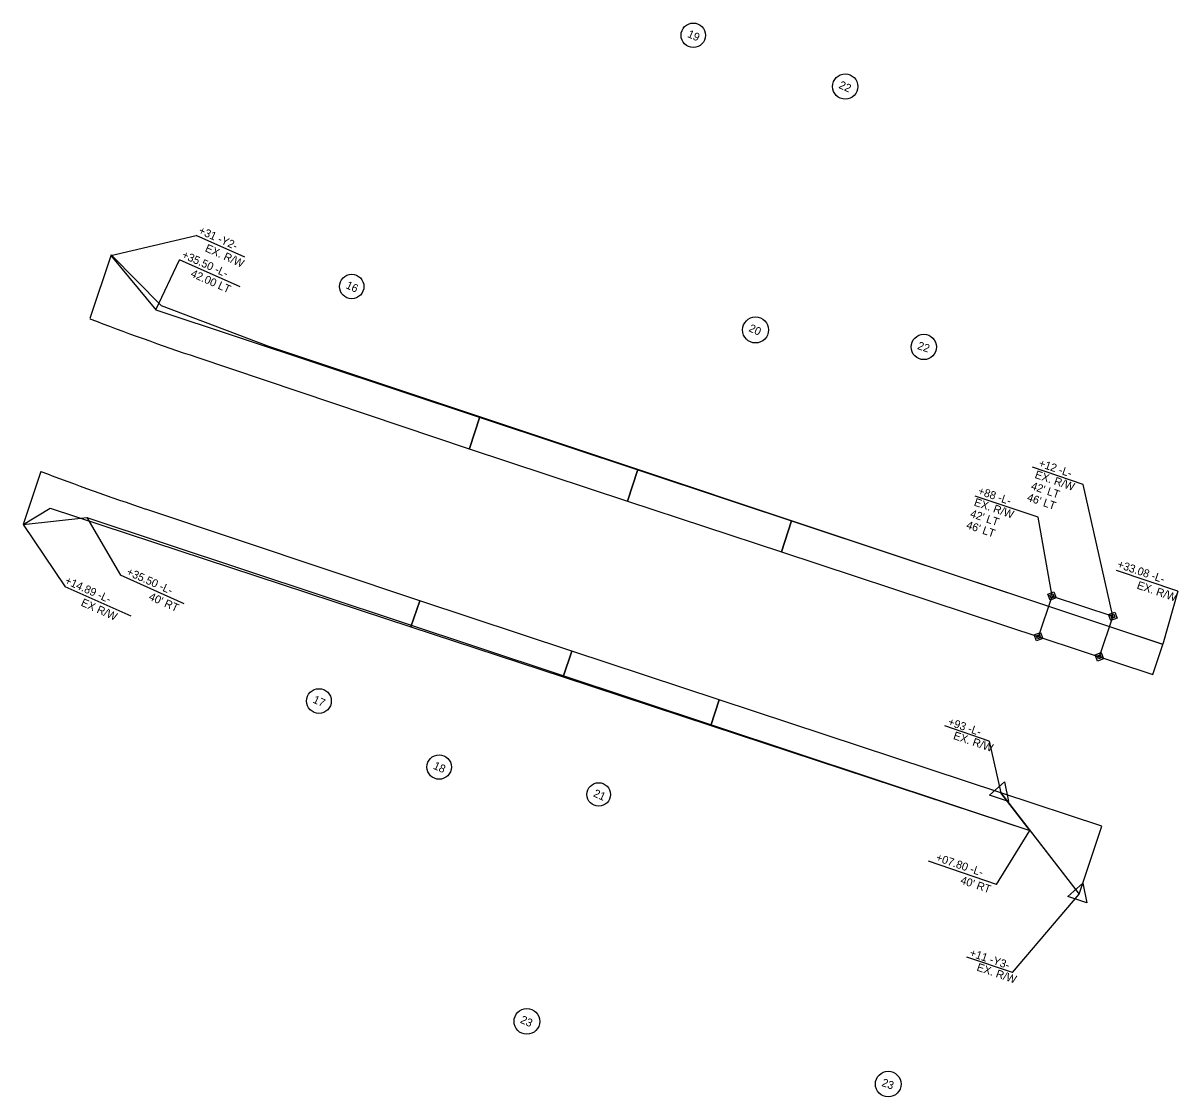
# Model space of a CAD drawing. Extents: x 2298011 to 2299093, y 599361 to 600353.
# Drawn here: x 2298660.4 to 2299093.1, y 599360.9 to 599763.4 of the extents above; entities that cross this region are included whole.
import ezdxf

# ---------------------------------------------------------------- set-up
doc = ezdxf.new("R2010")
doc.units = 0
for name, color, linetype in [('Prop Easement Construction', 7, 'Continuous'), ('Prop Easement Construction Station Offsets', 7, 'Continuous'), ('Prop Easement Permanent Drainage', 7, 'Continuous'), ('Prop Easement Permanent Drainage Station Offsets', 7, 'Continuous'), ('Prop Parcel Number Text', 7, 'Continuous'), ('Prop ROW Marker CELL', 7, 'Continuous'), ('Prop ROW Permanent Easement CELL', 7, 'Continuous'), ('Prop ROW RW Lines', 7, 'Continuous'), ('Prop ROW Station Offsets', 7, 'Continuous'), ('Scratch_Level_3', 7, 'Continuous'), ('Scratch_Level_6', 7, 'Continuous')]:
    doc.layers.add(name, color=color, linetype=linetype)

msp = doc.modelspace()

# ---------------------------------------------------------------- linework, layer by layer
at = {"layer": 'Prop Easement Construction'}
for p, q in [((2298693.31, 599676.25), (2298710.13, 599655.85)), ((2298710.13, 599655.85), (2299044.68, 599544.8)), ((2298660.37, 599575.48), (2298684.3, 599578.03)), ((2298684.3, 599578.03), (2299037.64, 599460.74)), ((2299067.46, 599537.24), (2299087.47, 599530.6))]:
    msp.add_line(p, q, dxfattribs=at)
at = {"layer": 'Prop Easement Construction Station Offsets'}
for p, q in [((2298743.43, 599675.6), (2298725.17, 599683.76)), ((2298741.77, 599664.48), (2298718.94, 599674.67)), ((2298720.77, 599545.73), (2298696.87, 599556.4)), ((2299093.11, 599550.44), (2299070.12, 599558.25)), ((2298700.86, 599541.03), (2298676.1, 599552.08)), ((2299025.16, 599440.51), (2298999.61, 599449.18))]:
    msp.add_line(p, q, dxfattribs=at)
for points in [[(2298693.31, 599676.25), (2298725.17, 599683.76)], [(2298710.13, 599655.85), (2298718.94, 599674.67)], [(2298684.3, 599578.03), (2298696.87, 599556.4)], [(2298660.37, 599575.48), (2298676.1, 599552.08)], [(2299093.11, 599550.44), (2299087.47, 599530.6)], [(2299025.16, 599440.51), (2299037.64, 599460.74)]]:
    msp.add_lwpolyline(points, dxfattribs=at)
at = {"layer": 'Prop Easement Permanent Drainage'}
for p, q in [((2299040.88, 599533.35), (2299045.94, 599548.6)), ((2299045.94, 599548.6), (2299068.72, 599541.04)), ((2299068.72, 599541.04), (2299063.67, 599525.82))]:
    msp.add_line(p, q, dxfattribs=at)
at = {"layer": 'Prop Easement Permanent Drainage Station Offsets'}
for p, q in [((2299057.56, 599590.48), (2299038.62, 599596.91)), ((2299068.72, 599541.04), (2299057.56, 599590.48)), ((2299040.69, 599578.12), (2299017.17, 599586.11))]:
    msp.add_line(p, q, dxfattribs=at)
msp.add_lwpolyline([(2299045.94, 599548.6), (2299040.69, 599578.12)], dxfattribs=at)
at = {"layer": 'Prop Parcel Number Text'}
for centre, radius in [((2298911.51, 599758.82), 4.57), ((2298968.45, 599739.59), 4.74), ((2298783.52, 599664.64), 4.58), ((2298934.85, 599648.36), 4.87), ((2298997.89, 599641.98), 4.74), ((2298771.23, 599509.25), 4.64), ((2298816.28, 599484.51), 4.58), ((2298876.06, 599474.24), 4.41), ((2298849.14, 599389.17), 4.81), ((2298984.55, 599365.67), 4.81)]:
    msp.add_circle(centre, radius, dxfattribs=at)
at = {"layer": 'Prop ROW Marker CELL'}
for p, q in [((2299045.94, 599548.6), (2299045.94, 599548.6)), ((2299068.72, 599541.04), (2299068.72, 599541.04)), ((2299040.88, 599533.35), (2299040.88, 599533.35)), ((2299063.67, 599525.82), (2299063.67, 599525.82)), ((2299026.73, 599474.84), (2299026.73, 599474.84)), ((2299056.1, 599436.88), (2299056.1, 599436.88))]:
    msp.add_line(p, q, dxfattribs=at)
for points in [[(2299022.48, 599474), (2299028.12, 599478.93), (2299029.58, 599471.59)], [(2299051.86, 599436.04), (2299057.49, 599440.97), (2299058.96, 599433.63)]]:
    msp.add_lwpolyline(points, close=True, dxfattribs=at)
at = {"layer": 'Prop ROW Permanent Easement CELL'}
for points in [[(2299045.24, 599547.02), (2299044.36, 599549.3), (2299046.64, 599550.18), (2299047.52, 599547.89)], [(2299045.59, 599547.81), (2299045.15, 599548.95), (2299046.29, 599549.39), (2299046.73, 599548.25)], [(2299068.01, 599539.46), (2299067.14, 599541.74), (2299069.42, 599542.61), (2299070.3, 599540.33)], [(2299068.37, 599540.25), (2299067.93, 599541.39), (2299069.07, 599541.83), (2299069.51, 599540.68)], [(2299040.18, 599531.78), (2299039.3, 599534.06), (2299041.58, 599534.93), (2299042.46, 599532.65)], [(2299040.53, 599532.56), (2299040.09, 599533.71), (2299041.23, 599534.14), (2299041.67, 599533)], [(2299062.96, 599524.25), (2299062.09, 599526.53), (2299064.37, 599527.4), (2299065.25, 599525.12)], [(2299063.32, 599525.04), (2299062.88, 599526.18), (2299064.02, 599526.61), (2299064.46, 599525.47)]]:
    msp.add_lwpolyline(points, close=True, dxfattribs=at)
at = {"layer": 'Prop ROW RW Lines'}
msp.add_line((2299026.73, 599474.84), (2299056.1, 599436.88), dxfattribs=at)
at = {"layer": 'Prop ROW Station Offsets'}
for p, q in [((2299022.42, 599494.26), (2299005.79, 599499.91)), ((2299031.18, 599407.45), (2299013.96, 599413.3))]:
    msp.add_line(p, q, dxfattribs=at)
for points in [[(2299022.42, 599494.26), (2299026.73, 599474.84)], [(2299031.18, 599407.45), (2299056.1, 599436.88)]]:
    msp.add_lwpolyline(points, dxfattribs=at)
at = {"layer": 'Scratch_Level_3'}
for p, q in [((2299064.62, 599462.32), (2299026.73, 599474.84)), ((2299026.73, 599474.84), (2299037.7, 599460.66)), ((2299037.7, 599460.66), (2299056.1, 599436.88)), ((2299056.1, 599436.88), (2299064.62, 599462.32))]:
    msp.add_line(p, q, dxfattribs=at)
at = {"layer": 'Scratch_Level_6'}
for p, q in [((2298693.4, 599676.53), (2298685.32, 599652.59)), ((2298831.52, 599615.83), (2298752.49, 599642.21)), ((2298725.44, 599638.12), (2298827.56, 599603.84)), ((2298827.6, 599603.94), (2298831.52, 599615.83)), ((2298831.52, 599615.83), (2298827.6, 599603.94)), ((2298890.76, 599596.06), (2298831.52, 599615.83)), ((2298827.56, 599603.84), (2298827.6, 599603.94)), ((2298827.6, 599603.94), (2298827.56, 599603.84)), ((2298827.56, 599603.84), (2298886.91, 599584.23)), ((2298667.05, 599595.34), (2298660.37, 599575.48)), ((2298886.91, 599584.23), (2298890.76, 599596.06)), ((2298890.76, 599596.06), (2298886.91, 599584.23)), ((2298948.28, 599576.86), (2298890.76, 599596.06)), ((2298660.37, 599575.48), (2298670.53, 599581.61)), ((2298670.53, 599581.61), (2298805.71, 599537.08)), ((2298886.91, 599584.23), (2298944.53, 599565.19)), ((2298808.98, 599546.79), (2298706.35, 599581.24)), ((2298944.53, 599565.19), (2298948.28, 599576.86)), ((2298948.28, 599576.86), (2298944.53, 599565.19)), ((2299087.41, 599530.42), (2298948.28, 599576.86)), ((2298944.53, 599565.19), (2299083.66, 599519.22)), ((2298805.71, 599537.08), (2298808.98, 599546.79)), ((2298808.98, 599546.79), (2298805.71, 599537.08)), ((2298865.95, 599527.96), (2298808.98, 599546.79)), ((2298805.71, 599537.08), (2298862.7, 599518.3)), ((2299083.66, 599519.22), (2299087.41, 599530.42)), ((2298862.7, 599518.3), (2298865.95, 599527.96)), ((2298865.95, 599527.96), (2298862.7, 599518.3)), ((2298921.15, 599509.72), (2298865.95, 599527.96)), ((2298862.7, 599518.3), (2298918.05, 599500.07)), ((2298918.05, 599500.07), (2298921.15, 599509.72)), ((2298921.15, 599509.72), (2298918.05, 599500.07)), ((2299026.73, 599474.84), (2298921.15, 599509.72)), ((2299037.7, 599460.66), (2299026.73, 599474.84))]:
    msp.add_line(p, q, dxfattribs=at)
for points in [[(2298752.49, 599642.21), (2298712.22, 599657.39), (2298693.4, 599676.53)], [(2298886.91, 599584.23), (2298886.91, 599584.23)], [(2298944.53, 599565.19), (2298944.53, 599565.19)], [(2298918.05, 599500.07), (2299037.19, 599460.83), (2299037.7, 599460.66)]]:
    msp.add_lwpolyline(points, dxfattribs=at)
for radius, start in [(963, 248.90345), (1023, 249.10276)]:
    msp.add_arc((2299031.95, 600551.04), radius, start, 251.44115, dxfattribs=at)

# ---------------------------------------------------------------- texts
at = {"layer": 'Prop Easement Construction Station Offsets'}
for s, rotation, p in [('+31 -Y2-', 335.9448, (2298725.82, 599684.61)), ('+35.50 -L-', 335.9448, (2298719.61, 599675.51)), ('EX. R/W', 335.9448, (2298728.3, 599677.93)), ('42.00 LT', 335.9448, (2298722.88, 599668.49)), ('+33.08 -L-', 341.2404, (2299070.14, 599559.34)), ('+35.50 -L-', 335.9448, (2298698.84, 599556.66)), ('+14.89 -L-', 335.9448, (2298675.73, 599553.39)), ('EX. R/W', 341.2404, (2299077.5, 599551.47)), ('EX R/W', 335.9448, (2298681.79, 599545.11)), ("40' RT", 335.9448, (2298707.21, 599547.36)), ('+07.80 -L-', 341.2404, (2299002.18, 599449.41)), ("40' RT", 341.2404, (2299011.37, 599440.92))]:
    msp.add_text(s, height=3, rotation=rotation, dxfattribs=at).set_placement(p)
at = {"layer": 'Prop Easement Permanent Drainage Station Offsets'}
for s, p in [('+12 -L-', (2299040.69, 599597.21)), ('EX. R/W', (2299039.24, 599592.95)), ("42' LT", (2299037.8, 599588.68)), ('+88 -L-', (2299017.92, 599586.85)), ("46' LT", (2299036.35, 599584.42)), ('EX. R/W', (2299016.47, 599582.59)), ("42' LT", (2299015.02, 599578.33)), ("46' LT", (2299013.58, 599574.07))]:
    msp.add_text(s, height=3, rotation=341.2404, dxfattribs=at).set_placement(p)
at = {"layer": 'Prop Parcel Number Text'}
for s, rotation, p in [('19', 335.9448, (2298909.04, 599758.28)), ('22', 335.9448, (2298965.78, 599739.14)), ('16', 335.9448, (2298781.04, 599664.1)), ('20', 335.9448, (2298932.03, 599647.97)), ('22', 341.2404, (2298995.27, 599641.28)), ('17', 335.9448, (2298768.68, 599508.75)), ('18', 335.9448, (2298813.79, 599483.98)), ('21', 335.9448, (2298873.78, 599473.61)), ('23', 335.9448, (2298846.39, 599388.76)), ('23', 341.2404, (2298981.84, 599365.01))]:
    msp.add_text(s, height=3, rotation=rotation, dxfattribs=at).set_placement(p)
at = {"layer": 'Prop ROW Station Offsets'}
for s, p in [('+93 -L-', (2299006.69, 599500.26)), ('EX. R/W', (2299008.7, 599495.09)), ('+11 -Y3-', (2299014.79, 599413.68)), ('EX. R/W', (2299017.47, 599408.28))]:
    msp.add_text(s, height=3, rotation=341.2404, dxfattribs=at).set_placement(p)

doc.saveas('drawing.dxf')
